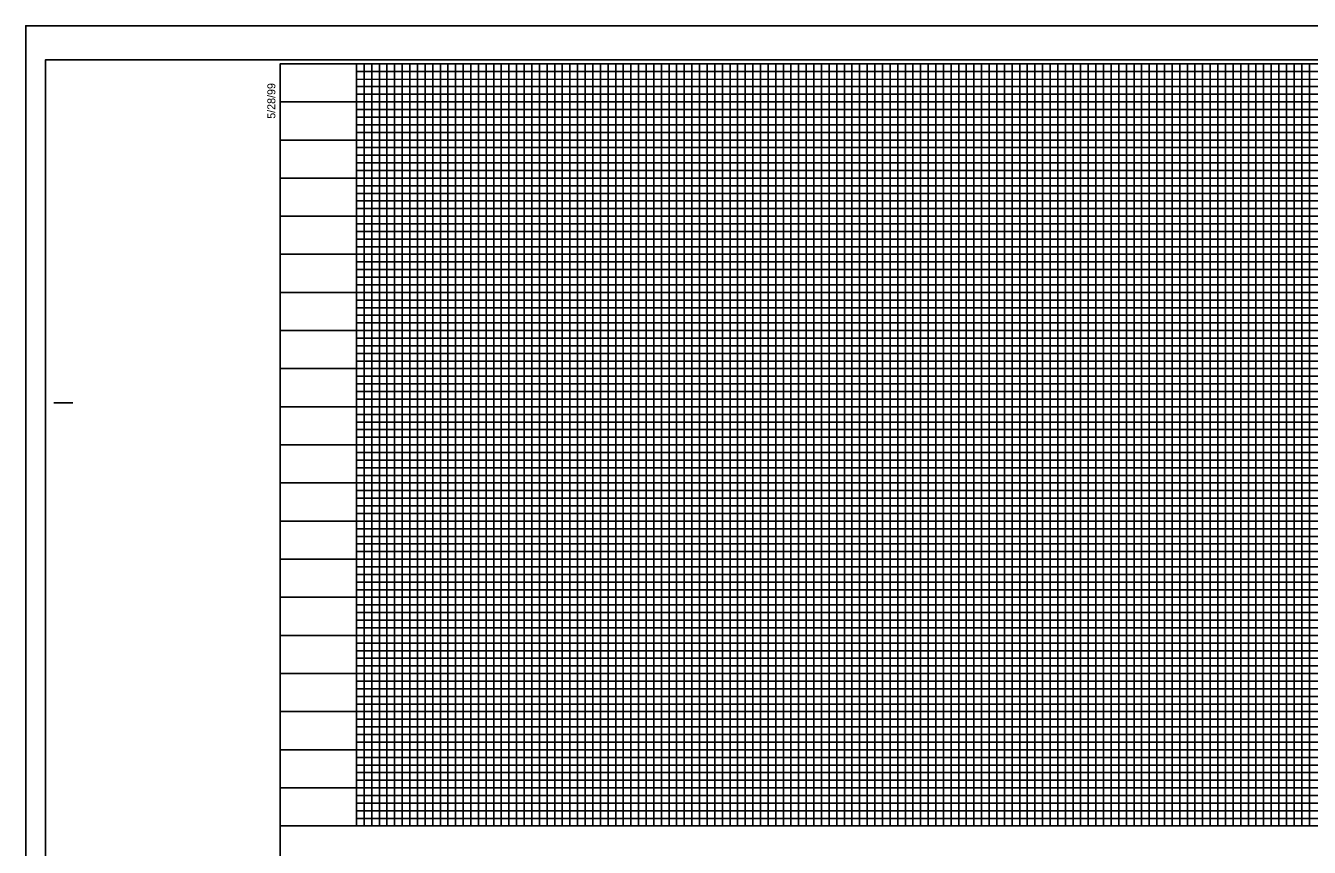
# Model space of a CAD drawing. Extents: x 2356353 to 2358037, y 848519 to 849619.
# Drawn here: x 2356353 to 2357195, y 849080 to 849619 of the extents above; entities that cross this region are included whole.
import ezdxf

# ---------------------------------------------------------------- set-up
doc = ezdxf.new("R2010")
doc.units = 0
for name, color, linetype in [('Default', 7, 'Continuous'), ('Sheet Cutting Line CELL', 7, 'Continuous'), ('Sheet DOT Grid CELL', 7, 'Continuous'), ('Sheet Layout Profile Border Port 1', 7, 'Continuous'), ('Sheet Plot Border Inside CELL', 7, 'Continuous'), ('Sheet Plot Border Outside CELL', 7, 'Continuous'), ('Sheet Profile CELL', 7, 'Continuous'), ('Sheet Profile Grid Major CELL', 7, 'Continuous'), ('Sheet Profile Grid Middle CELL', 7, 'Continuous'), ('Sheet Profile Grid Minor CELL', 7, 'Continuous')]:
    doc.layers.add(name, color=color, linetype=linetype)

msp = doc.modelspace()

# ---------------------------------------------------------------- linework, layer by layer
at = {"layer": 'Default'}
msp.add_lwpolyline([(2357970.19, 849409.89), (2357970.19, 849094.44), (2356570.19, 849094.44), (2356570.19, 849594.44), (2357820.14, 849594.44), (2357820.14, 849433.39), (2357970.19, 849433.39)], dxfattribs=at)
at = {"layer": 'Sheet Cutting Line CELL'}
for p, q in [((2358037.19, 849619.44), (2356353.19, 849619.44)), ((2356353.19, 849619.44), (2356353.19, 848519.44))]:
    msp.add_line(p, q, dxfattribs=at)
at = {"layer": 'Sheet DOT Grid CELL'}
for p, q in [((2356570.19, 849094.44), (2356570.19, 849594.44)), ((2356620.19, 849094.44), (2356620.19, 849594.44)), ((2356670.19, 849094.44), (2356670.19, 849594.44)), ((2356720.19, 849094.44), (2356720.19, 849594.44)), ((2356770.19, 849094.44), (2356770.19, 849594.44)), ((2356820.19, 849094.44), (2356820.19, 849594.44)), ((2356870.19, 849094.44), (2356870.19, 849594.44)), ((2356920.19, 849094.44), (2356920.19, 849594.44)), ((2356970.19, 849094.44), (2356970.19, 849594.44)), ((2357020.19, 849094.44), (2357020.19, 849594.44)), ((2357070.19, 849094.44), (2357070.19, 849594.44)), ((2357120.19, 849094.44), (2357120.19, 849594.44)), ((2357170.19, 849094.44), (2357170.19, 849594.44)), ((2357820.14, 849544.44), (2356520.19, 849544.44)), ((2357820.14, 849494.44), (2356520.19, 849494.44)), ((2357820.19, 849444.44), (2356520.19, 849444.44)), ((2358020.19, 849394.44), (2356520.19, 849394.44)), ((2358020.19, 849344.44), (2356520.19, 849344.44)), ((2358020.19, 849294.44), (2356520.19, 849294.44)), ((2358020.19, 849244.44), (2356520.19, 849244.44)), ((2358020.19, 849194.44), (2356520.19, 849194.44)), ((2358020.19, 849144.44), (2356520.19, 849144.44))]:
    msp.add_line(p, q, dxfattribs=at)
at = {"layer": 'Sheet Layout Profile Border Port 1'}
msp.add_lwpolyline([(2356570.19, 849433.39), (2356570.19, 849094.44), (2357970.19, 849094.44), (2357970.19, 849409.89)], dxfattribs=at)
at = {"layer": 'Sheet Plot Border Inside CELL'}
msp.add_lwpolyline([(2356366.19, 848541.89), (2358032.69, 848541.89), (2358032.69, 849596.99), (2356366.19, 849596.99)], close=True, dxfattribs=at)
at = {"layer": 'Sheet Plot Border Outside CELL'}
msp.add_lwpolyline([(2356353.19, 848519.44), (2358037.19, 848519.44), (2358037.19, 849619.44), (2356353.19, 849619.44)], close=True, dxfattribs=at)
at = {"layer": 'Sheet Profile CELL'}
for p, q in [((2356371.69, 849371.94), (2356384.19, 849371.94)), ((2356520.19, 849094.44), (2358020.19, 849094.44))]:
    msp.add_line(p, q, dxfattribs=at)
msp.add_lwpolyline([(2358020.19, 849594.44), (2356520.19, 849594.44), (2356520.19, 848544.44), (2358020.19, 848544.44)], close=True, dxfattribs=at)
at = {"layer": 'Sheet Profile Grid Major CELL'}
for points in [[(2356570.19, 849594.44), (2356570.19, 849094.44), (2356620.19, 849094.44), (2356620.19, 849594.44), (2356670.19, 849594.44), (2356670.19, 849094.44), (2356720.19, 849094.44), (2356720.19, 849594.44), (2356770.19, 849594.44), (2356770.19, 849094.44), (2356820.19, 849094.44), (2356820.19, 849594.44), (2356870.19, 849594.44), (2356870.19, 849094.44), (2356920.19, 849094.44), (2356920.19, 849594.44), (2356970.19, 849594.44), (2356970.19, 849094.44), (2357020.19, 849094.44), (2357020.19, 849594.44), (2357070.19, 849594.44), (2357070.19, 849094.44), (2357120.19, 849094.44), (2357120.19, 849594.44), (2357170.19, 849594.44), (2357170.19, 849094.44), (2357220.19, 849094.44)], [(2356520.19, 849544.44), (2357820.19, 849544.44)], [(2357820.19, 849494.44), (2356520.19, 849494.44), (2356520.19, 849444.44), (2357820.19, 849444.44)], [(2358020.19, 849394.44), (2356520.19, 849394.44), (2356520.19, 849344.44), (2358020.19, 849344.44)], [(2358020.19, 849294.44), (2356520.19, 849294.44), (2356520.19, 849244.44), (2358020.19, 849244.44)], [(2358020.19, 849194.44), (2356520.19, 849194.44), (2356520.19, 849194.44), (2356520.19, 849144.44), (2358020.19, 849144.44)]]:
    msp.add_lwpolyline(points, dxfattribs=at)
at = {"layer": 'Sheet Profile Grid Middle CELL'}
msp.add_line((2356520.19, 849569.44), (2357820.14, 849569.44), dxfattribs=at)
for points in [[(2356595.19, 849594.44), (2356595.19, 849094.44), (2356645.19, 849094.44), (2356645.19, 849594.44), (2356695.19, 849594.44), (2356695.19, 849094.44), (2356745.19, 849094.44), (2356745.19, 849594.44), (2356795.19, 849594.44), (2356795.19, 849094.44), (2356845.19, 849094.44), (2356845.19, 849594.44), (2356895.19, 849594.44), (2356895.19, 849094.44), (2356945.19, 849094.44), (2356945.19, 849594.44), (2356995.19, 849594.44), (2356995.19, 849094.44), (2357045.19, 849094.44), (2357045.19, 849594.44), (2357095.19, 849594.44), (2357095.19, 849094.44), (2357145.19, 849094.44), (2357145.19, 849094.44), (2357145.19, 849594.44), (2357195.19, 849594.44), (2357195.19, 849094.44), (2357245.19, 849094.44)], [(2357820.19, 849519.44), (2356520.19, 849519.44), (2356520.19, 849469.44), (2357820.19, 849469.44)], [(2357820.19, 849419.44), (2356520.19, 849419.44), (2356520.19, 849369.44), (2357845.19, 849369.44)], [(2358020.19, 849319.44), (2356520.19, 849319.44), (2356520.19, 849269.44), (2358020.19, 849269.44)], [(2358020.19, 849219.44), (2356520.19, 849219.44), (2356520.19, 849169.44), (2358020.19, 849169.44)], [(2358020.19, 849119.44), (2356520.19, 849119.44)]]:
    msp.add_lwpolyline(points, dxfattribs=at)
at = {"layer": 'Sheet Profile Grid Minor CELL'}
for p, q in [((2356570.19, 849589.44), (2357820.19, 849589.44)), ((2356570.19, 849584.44), (2356570.19, 849584.44)), ((2357820.19, 849584.44), (2356570.19, 849584.09)), ((2356570.19, 849579.44), (2357820.19, 849579.44)), ((2357820.14, 849459.44), (2356570.19, 849459.44)), ((2357820.19, 849454.44), (2356570.19, 849454.44)), ((2357820.19, 849449.44), (2356570.19, 849449.44)), ((2356570.19, 849439.44), (2357820.19, 849439.44)), ((2357820.19, 849434.44), (2356570.19, 849434.44)), ((2356570.19, 849429.44), (2357820.19, 849429.44)), ((2357970.19, 849409.44), (2356570.19, 849409.44)), ((2356570.19, 849404.44), (2357970.19, 849404.44)), ((2357970.19, 849384.44), (2356570.19, 849384.44)), ((2356570.19, 849379.44), (2357970.19, 849379.44)), ((2357970.19, 849359.44), (2356570.19, 849359.44)), ((2356570.19, 849354.44), (2357970.19, 849354.44)), ((2357970.19, 849349.44), (2356570.19, 849349.44)), ((2356570.19, 849339.44), (2357970.19, 849339.44)), ((2357970.19, 849334.44), (2356570.19, 849334.44)), ((2356570.19, 849329.44), (2357970.19, 849329.44)), ((2357970.19, 849324.44), (2356570.19, 849324.44)), ((2356570.19, 849314.44), (2357970.19, 849314.44)), ((2357970.19, 849309.44), (2356570.19, 849309.44)), ((2356570.19, 849304.44), (2357970.19, 849304.44)), ((2357970.19, 849299.44), (2356570.19, 849299.44)), ((2356570.19, 849289.44), (2357970.19, 849289.44)), ((2357970.19, 849284.44), (2356570.19, 849284.44)), ((2356570.19, 849279.44), (2357970.19, 849279.44)), ((2357970.19, 849274.44), (2356570.19, 849274.44)), ((2356570.19, 849264.44), (2357970.19, 849264.44)), ((2357970.19, 849259.44), (2356570.19, 849259.44)), ((2356570.19, 849254.44), (2357970.19, 849254.44)), ((2357970.19, 849249.44), (2356570.19, 849249.44)), ((2356570.19, 849239.44), (2357970.19, 849239.44)), ((2357970.19, 849234.44), (2356570.19, 849234.44)), ((2356570.19, 849229.44), (2357970.19, 849229.44)), ((2357970.19, 849224.44), (2356570.19, 849224.44)), ((2356570.19, 849214.44), (2357970.19, 849214.44)), ((2357970.19, 849209.44), (2356570.19, 849209.44)), ((2357970.19, 849204.44), (2356570.19, 849204.44)), ((2357970.19, 849199.44), (2356570.19, 849199.44)), ((2356570.19, 849189.44), (2357970.19, 849189.44)), ((2357970.19, 849184.44), (2356570.19, 849184.44)), ((2356570.19, 849179.44), (2357970.19, 849179.44)), ((2357970.19, 849174.44), (2356570.19, 849174.44)), ((2356570.19, 849164.44), (2357970.19, 849164.44)), ((2357970.19, 849159.44), (2356570.19, 849159.44)), ((2356570.19, 849154.44), (2357970.19, 849154.44)), ((2357970.19, 849149.44), (2356570.19, 849149.44)), ((2356570.19, 849139.44), (2357970.19, 849139.44)), ((2357970.19, 849134.44), (2356570.19, 849134.44)), ((2356570.19, 849129.44), (2357970.19, 849129.44)), ((2357970.19, 849124.44), (2356570.19, 849124.44)), ((2356570.19, 849114.44), (2357970.19, 849114.44)), ((2357970.19, 849109.44), (2356570.19, 849109.44)), ((2356570.19, 849104.44), (2357970.19, 849104.44))]:
    msp.add_line(p, q, dxfattribs=at)
for points in [[(2356575.19, 849594.44), (2356575.19, 849094.44), (2356580.19, 849094.44), (2356580.19, 849594.44), (2356585.19, 849594.44), (2356585.19, 849094.44), (2356590.19, 849094.44), (2356590.19, 849594.44), (2356600.19, 849594.44), (2356600.19, 849094.44), (2356605.19, 849094.44), (2356605.19, 849594.44), (2356610.19, 849594.44), (2356610.19, 849094.44), (2356615.19, 849094.44), (2356625.19, 849094.44), (2356630.19, 849094.44), (2356630.19, 849594.44), (2356635.19, 849594.44), (2356635.19, 849094.44), (2356640.19, 849094.44), (2356640.19, 849594.44), (2356650.19, 849594.44), (2356650.19, 849094.44), (2356655.19, 849094.44), (2356655.19, 849594.44), (2356660.19, 849594.44), (2356660.19, 849094.44), (2356665.19, 849094.44), (2356665.19, 849594.44), (2356675.19, 849594.44), (2356675.19, 849094.44), (2356680.19, 849094.44), (2356680.19, 849594.44), (2356685.19, 849594.44), (2356685.19, 849094.44), (2356690.19, 849094.44), (2356690.19, 849594.44), (2356700.19, 849594.44), (2356700.19, 849094.44), (2356705.19, 849094.44), (2356705.19, 849594.44), (2356710.19, 849594.44), (2356710.19, 849094.44), (2356715.19, 849094.44), (2356715.19, 849594.44), (2356725.19, 849594.44), (2356725.19, 849094.44), (2356730.19, 849094.44), (2356730.19, 849594.44), (2356735.19, 849594.44), (2356735.19, 849094.44), (2356740.19, 849094.44), (2356740.19, 849594.44), (2356750.19, 849594.44), (2356750.19, 849094.44), (2356755.19, 849094.44), (2356755.19, 849594.44), (2356760.19, 849594.44), (2356760.19, 849094.44), (2356765.19, 849094.44), (2356765.19, 849594.44), (2356775.19, 849594.44), (2356775.19, 849094.44), (2356780.19, 849094.44), (2356780.19, 849594.44), (2356785.19, 849594.44), (2356785.19, 849094.44)], [(2356615.19, 849094.44), (2356615.19, 849594.44), (2356625.19, 849594.44), (2356625.19, 849094.44)], [(2356785.19, 849094.44), (2356790.19, 849094.44), (2356790.19, 849594.44), (2356800.19, 849594.44), (2356800.19, 849094.44), (2356805.19, 849094.44), (2356805.19, 849594.44), (2356810.19, 849594.44), (2356810.19, 849094.44), (2356815.19, 849094.44), (2356815.19, 849594.44), (2356825.19, 849594.44), (2356825.19, 849094.44), (2356830.19, 849094.44), (2356830.19, 849594.44), (2356835.19, 849594.44), (2356835.19, 849094.44), (2356840.19, 849094.44), (2356840.19, 849594.44), (2356850.19, 849594.44), (2356850.19, 849094.44), (2356855.19, 849094.44), (2356855.19, 849594.44), (2356860.19, 849594.44), (2356860.19, 849094.44), (2356865.19, 849094.44), (2356865.19, 849594.44), (2356875.19, 849594.44), (2356875.19, 849094.44), (2356880.19, 849094.44), (2356880.19, 849594.44), (2356885.19, 849594.44), (2356885.19, 849094.44), (2356890.19, 849094.44), (2356890.19, 849594.44), (2356900.19, 849594.44), (2356900.19, 849094.44), (2356905.19, 849094.44), (2356905.19, 849594.44), (2356910.19, 849594.44), (2356910.19, 849094.44), (2356915.19, 849094.44), (2356915.19, 849594.44), (2356925.19, 849594.44), (2356925.19, 849094.44), (2356930.19, 849094.44), (2356930.19, 849594.44), (2356935.19, 849594.44), (2356935.19, 849094.44), (2356940.19, 849094.44), (2356940.19, 849594.44), (2356950.19, 849594.44), (2356950.19, 849094.44), (2356955.19, 849094.44), (2356955.19, 849594.44), (2356960.19, 849594.44), (2356960.19, 849094.44), (2356965.19, 849094.44), (2356965.19, 849594.44), (2356975.19, 849594.44), (2356975.19, 849094.44), (2356980.19, 849094.44), (2356980.19, 849594.44), (2356985.19, 849594.44), (2356985.19, 849094.44), (2356990.19, 849094.44), (2356990.19, 849594.44), (2357000.19, 849594.44), (2357000.19, 849094.44), (2357005.19, 849094.44), (2357005.19, 849594.44), (2357010.19, 849594.44), (2357010.19, 849094.44), (2357015.19, 849094.44), (2357015.19, 849594.44), (2357025.19, 849594.44), (2357025.19, 849094.44), (2357030.19, 849094.44), (2357030.19, 849594.44), (2357035.19, 849594.44), (2357035.19, 849094.44), (2357040.19, 849094.44), (2357040.19, 849594.44), (2357050.19, 849594.44), (2357050.19, 849094.44), (2357055.19, 849094.44), (2357055.19, 849594.44), (2357060.19, 849594.44), (2357060.19, 849094.44), (2357065.19, 849094.44), (2357065.19, 849594.44), (2357075.19, 849594.44), (2357075.19, 849094.44), (2357080.19, 849094.44), (2357080.19, 849594.44), (2357085.19, 849594.44), (2357085.19, 849094.44), (2357090.19, 849094.44), (2357090.19, 849594.44), (2357100.19, 849594.44)], [(2357100.19, 849594.44), (2357100.19, 849094.44), (2357105.19, 849094.44), (2357105.19, 849594.44), (2357110.19, 849594.44), (2357110.19, 849094.44), (2357115.19, 849094.44), (2357115.19, 849594.44), (2357125.19, 849594.44), (2357125.19, 849094.44), (2357130.19, 849094.44), (2357130.19, 849594.44), (2357135.19, 849594.44), (2357135.19, 849094.44), (2357140.19, 849094.44), (2357140.19, 849594.44), (2357150.19, 849594.44), (2357150.19, 849094.44), (2357155.19, 849094.44), (2357155.19, 849594.44), (2357160.19, 849594.44), (2357160.19, 849094.44), (2357165.19, 849094.44), (2357165.19, 849594.44), (2357175.19, 849594.44), (2357175.19, 849094.44), (2357180.19, 849094.44), (2357180.19, 849594.44), (2357185.19, 849594.44), (2357185.19, 849094.44), (2357190.19, 849094.44), (2357190.19, 849594.44), (2357200.19, 849594.44)], [(2357820.19, 849574.44), (2356570.19, 849574.44), (2356570.19, 849564.44), (2357820.19, 849564.44)], [(2357820.14, 849559.44), (2356570.19, 849559.44), (2356570.19, 849554.44), (2357820.19, 849554.44)], [(2357820.19, 849549.44), (2356570.19, 849549.44), (2356570.19, 849539.44), (2357820.19, 849539.44)], [(2357820.19, 849534.44), (2356570.19, 849534.44), (2356570.19, 849529.44), (2357820.19, 849529.44)], [(2357820.19, 849524.44), (2356570.19, 849524.44), (2356570.19, 849514.44), (2357820.19, 849514.44)], [(2357820.19, 849509.44), (2356570.19, 849509.44), (2356570.19, 849504.44), (2357820.19, 849504.44)], [(2357820.19, 849499.44), (2356570.19, 849499.44), (2356570.19, 849489.44), (2357820.19, 849489.44)], [(2357820.19, 849484.34), (2356570.29, 849484.34), (2356570.29, 849479.44), (2357820.19, 849479.44)], [(2357820.19, 849474.44), (2356570.19, 849474.44), (2356570.19, 849464.44), (2357820.19, 849464.44)], [(2357820.19, 849424.44), (2356570.19, 849424.44), (2356570.19, 849414.44), (2357820.19, 849414.44)], [(2357970.19, 849399.44), (2356570.19, 849399.44), (2356570.19, 849389.44), (2357970.19, 849389.44)], [(2357970.19, 849374.44), (2356570.19, 849374.44), (2356570.19, 849364.44), (2357970.19, 849364.44)], [(2357970.19, 849099.44), (2356570.19, 849099.44)]]:
    msp.add_lwpolyline(points, dxfattribs=at)

# ---------------------------------------------------------------- texts
at = {"layer": 'Sheet Profile CELL'}
msp.add_text('5/28/99', height=5.25, rotation=90, dxfattribs=at).set_placement((2356516.95, 849558.35))

doc.saveas('drawing.dxf')
